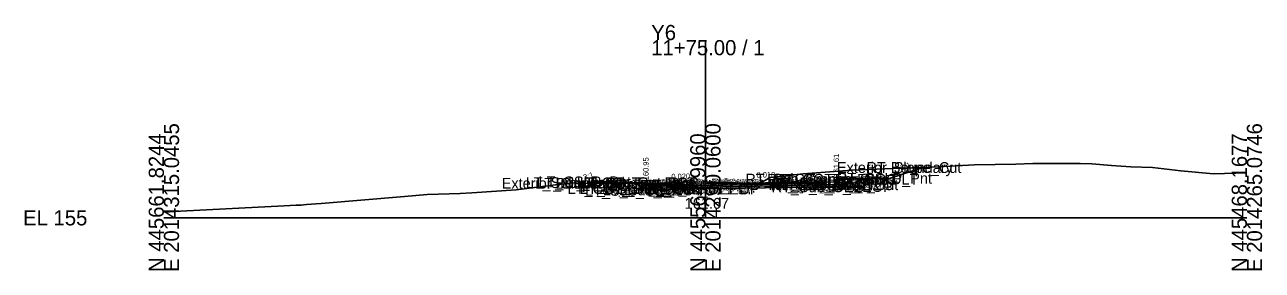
# Model space of a CAD drawing. Extents: x -26 to 203, y -10 to 4529.
# Drawn here: x -25.7 to 202.8, y 3490.3 to 3535.7 of the extents above; entities that cross this region are included whole.
import ezdxf

# ---------------------------------------------------------------- set-up
doc = ezdxf.new("R2010")
doc.units = 0
for name, color, linetype in [('Default', 7, 'Continuous'), ('Exist Cross Section Cell', 7, 'Continuous'), ('Exist XS Center Line Elevation Label', 7, 'Continuous'), ('Exist XS Ground Line', 7, 'Continuous'), ('Prop CMT Conc Surface', 7, 'Continuous'), ('Prop CMT Concrete Structures', 7, 'Continuous'), ('Prop CMT Pvmt Course 1', 7, 'Continuous'), ('Prop CMT Pvmt Course 1 CG', 7, 'Continuous'), ('Prop CMT Pvmt Course 2', 7, 'Continuous'), ('Prop CMT Pvmt Course 3', 7, 'Continuous'), ('Prop CMT Pvmt Surface', 7, 'Continuous'), ('Prop CMT Slope Grass', 7, 'Continuous'), ('Prop CMT Subgrade Earthwork', 7, 'Continuous'), ('Prop XS Earthwork Shape', 7, 'Continuous'), ('Prop XS Hydro Elevations', 7, 'Continuous'), ('Prop XS SE Text', 7, 'Continuous'), ('Prop XS Side Slope Text', 7, 'Continuous'), ('Scratch_Level_0', 7, 'Continuous')]:
    doc.layers.add(name, color=color, linetype=linetype)

msp = doc.modelspace()

# ---------------------------------------------------------------- linework, layer by layer
at = {"layer": 'Exist Cross Section Cell'}
for p, q in [((100, 3500), (100, 3532.84)), ((0, 3500), (100, 3500)), ((100, 3500), (200, 3500))]:
    msp.add_line(p, q, dxfattribs=at)
at = {"layer": 'Exist XS Ground Line'}
msp.add_lwpolyline([(0, 3501.07), (3.09, 3501.2), (22.19, 3502.2), (24.42, 3502.31), (25.33, 3502.36), (25.78, 3502.41), (26.34, 3502.46), (29.04, 3502.66), (44.41, 3503.95), (48.65, 3504.28), (54.74, 3504.48), (56.86, 3504.64), (65.08, 3505.17), (73.28, 3506.19), (75.39, 3506.48), (77.21, 3506.39), (90.34, 3506.37), (95.88, 3506.56), (100.18, 3506.67), (108.03, 3506.36), (109.71, 3506.26), (110.61, 3506.73), (112, 3507.43), (118.09, 3508.13), (127.04, 3508.83), (134.66, 3509.09), (137.48, 3509.17), (138.13, 3509.21), (138.73, 3509.24), (139.6, 3509.26), (149.68, 3509.77), (157.33, 3509.92), (160.45, 3510.05), (167.76, 3510.04), (169.21, 3510.04), (171.39, 3510), (174.97, 3509.68), (178.58, 3509.4), (182.56, 3509.31), (187.8, 3508.71), (193.82, 3508.1), (200, 3508.29)], dxfattribs=at)
at = {"layer": 'Prop CMT Conc Surface'}
for points in [[(89.01, 3505.95), (89, 3506.45), (88.5, 3506.45)], [(91.01, 3506.07), (89.01, 3505.95)], [(122.17, 3506.65), (124.17, 3506.61)], [(124.17, 3506.61), (124.18, 3507.11), (124.68, 3507.11)]]:
    msp.add_lwpolyline(points, dxfattribs=at)
at = {"layer": 'Prop CMT Concrete Structures'}
for points in [[(91.01, 3506.07), (89.01, 3505.95), (89, 3506.45), (88.5, 3506.45)], [(88.5, 3506.45), (88.51, 3505.43), (91.01, 3505.48)], [(91.01, 3505.48), (91.01, 3506.07)], [(122.17, 3506.65), (124.17, 3506.61), (124.18, 3507.11), (124.68, 3507.11)], [(124.68, 3507.11), (124.67, 3506.11), (122.17, 3506.07)], [(122.17, 3506.07), (122.17, 3506.65)]]:
    msp.add_lwpolyline(points, dxfattribs=at)
at = {"layer": 'Prop CMT Pvmt Course 1'}
for points in [[(100, 3506.25), (91.01, 3506.07)], [(91.01, 3506.07), (91.01, 3505.82)], [(91.01, 3505.82), (100, 3506)], [(100, 3506.25), (122.17, 3506.65)], [(122.17, 3506.4), (100, 3506)], [(100, 3506), (100, 3506.25)], [(100, 3506), (100, 3506.25)], [(122.17, 3506.65), (122.17, 3506.4)]]:
    msp.add_lwpolyline(points, dxfattribs=at)
msp.add_lwpolyline([(100, 3506), (100, 3506.12), (100, 3506.12), (100, 3506)], close=True, dxfattribs=at)
msp.add_lwpolyline([(100, 3506), (100, 3506.12), (100, 3506.12), (100, 3506)], close=True, dxfattribs=at)
at = {"layer": 'Prop CMT Pvmt Course 1 CG'}
for points in [[(122.17, 3506.07), (125.17, 3506.12), (125.5, 3505.79)], [(122.17, 3505.73), (122.17, 3506.07)], [(125.5, 3505.79), (122.17, 3505.73)], [(91.01, 3505.48), (88.01, 3505.42), (87.66, 3505.08)], [(87.66, 3505.08), (91.01, 3505.15)], [(91.01, 3505.15), (91.01, 3505.48)]]:
    msp.add_lwpolyline(points, dxfattribs=at)
at = {"layer": 'Prop CMT Pvmt Course 2'}
for points in [[(100, 3506), (91.01, 3505.82)], [(91.01, 3505.82), (91.01, 3505.48)], [(100, 3506), (122.17, 3506.4)], [(122.17, 3506.07), (100, 3505.66)], [(100, 3505.66), (100, 3506)], [(100, 3505.66), (100, 3506)], [(122.17, 3506.4), (122.17, 3506.07)], [(91.01, 3505.48), (100, 3505.66)]]:
    msp.add_lwpolyline(points, dxfattribs=at)
at = {"layer": 'Prop CMT Pvmt Course 3'}
for points in [[(100, 3505.66), (122.17, 3506.07)], [(122.17, 3505.73), (100, 3505.33)], [(122.17, 3506.07), (122.17, 3505.73)], [(100, 3505.66), (91.01, 3505.48)], [(91.01, 3505.48), (91.01, 3505.15)], [(91.01, 3505.15), (100, 3505.33)], [(100, 3505.33), (100, 3505.66)], [(100, 3505.33), (100, 3505.66)]]:
    msp.add_lwpolyline(points, dxfattribs=at)
at = {"layer": 'Prop CMT Pvmt Surface'}
for points in [[(100, 3506.25), (91.01, 3506.07)], [(100, 3506.25), (122.17, 3506.65)]]:
    msp.add_lwpolyline(points, dxfattribs=at)
at = {"layer": 'Prop CMT Slope Grass'}
for points in [[(124.68, 3507.11), (134.18, 3507.3), (140.15, 3509.29)], [(88.5, 3506.45), (79, 3506.64), (78.25, 3506.38)]]:
    msp.add_lwpolyline(points, dxfattribs=at)
at = {"layer": 'Prop CMT Subgrade Earthwork'}
for points in [[(91.01, 3505.15), (87.66, 3505.08), (86.26, 3506.49)], [(100, 3505.33), (122.17, 3505.73)], [(122.17, 3505.73), (125.5, 3505.79), (126.86, 3507.15)], [(100, 3505.33), (91.01, 3505.15)]]:
    msp.add_lwpolyline(points, dxfattribs=at)
at = {"layer": 'Prop XS Earthwork Shape'}
for points in [[(127.04, 3508.83), (134.66, 3509.09), (137.48, 3509.17), (138.13, 3509.21), (138.73, 3509.24), (139.6, 3509.26), (140.15, 3509.29), (134.18, 3507.3), (126.86, 3507.15), (124.68, 3507.11), (124.18, 3507.11), (124.17, 3506.61), (122.17, 3506.65), (110.03, 3506.43), (110.61, 3506.73), (112, 3507.43), (118.09, 3508.13)], [(86.37, 3506.37), (86.26, 3506.49), (79, 3506.64), (78.25, 3506.38)], [(87.66, 3505.08), (86.37, 3506.37), (88.5, 3506.37), (88.51, 3505.43), (91.01, 3505.48), (91.01, 3506.07), (100, 3506.25), (107.46, 3506.38), (108.03, 3506.36), (109.71, 3506.26), (110.03, 3506.43), (122.17, 3506.65), (122.17, 3506.07), (124.67, 3506.11), (124.68, 3507.11), (126.86, 3507.15), (125.5, 3505.79), (122.17, 3505.73), (100, 3505.33), (91.01, 3505.15)], [(88.5, 3506.37), (89, 3506.37), (89.01, 3505.95), (91.01, 3506.07), (91.01, 3505.48), (88.51, 3505.43)], [(100, 3506.25), (107.46, 3506.38), (100.18, 3506.67), (95.88, 3506.56), (90.34, 3506.37), (89, 3506.37), (89.01, 3505.95), (91.01, 3506.07)], [(124.17, 3506.61), (124.18, 3507.11), (124.68, 3507.11), (124.67, 3506.11), (122.17, 3506.07), (122.17, 3506.65)]]:
    msp.add_lwpolyline(points, close=True, dxfattribs=at)

# ---------------------------------------------------------------- texts
at = {"layer": 'Default'}
msp.add_text('-', height=0.0001, dxfattribs=at).set_placement((0, 3500))
at = {"layer": 'Exist Cross Section Cell'}
for s, p in [('Y6', (90, 3532.84)), ('11+75.00 / 1', (90, 3530.04)), ('EL 155', (-26, 3498.6))]:
    msp.add_text(s, height=2.8, dxfattribs=at).set_placement(p)
for s, p in [('E 2014315.0455', (2.8, 3490)), ('E 2014290.0600', (102.8, 3490)), ('E 2014265.0746', (202.8, 3490)), ('N 445661.8244', (0, 3490)), ('N 445564.9960', (100, 3490)), ('N 445468.1677', (200, 3490))]:
    msp.add_text(s, height=2.8, rotation=90, dxfattribs=at).set_placement(p)
at = {"layer": 'Exist XS Center Line Elevation Label'}
msp.add_text('161.67', height=2, dxfattribs=at).set_placement((96.18, 3501.67))
at = {"layer": 'Prop XS Hydro Elevations'}
for s, p in [('160.95', (89.51, 3506.95)), ('161.61', (124.67, 3507.61))]:
    msp.add_text(s, height=1, rotation=90, dxfattribs=at).set_placement(p)
at = {"layer": 'Prop XS SE Text'}
for s, rotation, p in [('0.020', 1.1458, (93.73, 3507.12)), ('0.018', 1.0447, (109.45, 3507.42))]:
    msp.add_text(s, height=1, rotation=rotation, dxfattribs=at).set_placement(p)
at = {"layer": 'Prop XS Side Slope Text'}
for p in [(77.64, 3506.97), (136.18, 3508.75)]:
    msp.add_text('3:1', height=1, rotation=18.4332, dxfattribs=at).set_placement(p)
at = {"layer": 'Scratch_Level_0'}
for s, p in [('Exterior Boundary', (124.29, 3508.29)), ('RT_Slope_Cut', (129.74, 3508.29)), ('RT_Sub_Trench_Out_DLT', (107.38, 3506.15)), ('RT_CG_Top_Face', (111.39, 3506.11)), ('RT_CG_Top_BOC', (112.91, 3506.11)), ('RT_CSLP_Pnt', (124.3, 3506.3)), ('Exterior Boundary', (62.39, 3505.38)), ('LT_Sub_Trench_Out_DLT', (66.82, 3505.49)), ('LT_Slope_Fill', (68.77, 3505.38)), ('LT_CSLP_Pnt', (69.18, 3505.64)), ('LT_CG1_Shelf_Out', (74.56, 3504.42)), ('LT_CG_Top_Face', (76.26, 3505.45)), ('LT_CG_Top_BOC', (76.79, 3505.45)), ('LT_CG_Bot_BOC', (76.82, 3504.43)), ('LT_CG_Top_Gut', (77.24, 3504.95)), ('LT_Sub_OEOP', (77.78, 3504.08)), ('LT_CG_Bot_IE', (80.92, 3504.48)), ('LT_Sub_OEOT', (81.08, 3504.15)), ('LT_PV2_OEOT', (81.18, 3504.82)), ('LT_PV3_OEOT', (81.18, 3504.48)), ('LT_PV1_OEOT', (81.75, 3505.07)), ('RT_Sub_OEEOP', (89.17, 3504.33)), ('LT_Sub_OEEOP', (89.21, 3504.33)), ('RT_PV2_OEEOP', (89.26, 3505)), ('RT_PV3_OEEOP', (89.26, 3504.66)), ('LT_PV2_OEEOP', (89.31, 3505)), ('LT_PV3_OEEOP', (89.31, 3504.66)), ('RT_PV1_OEEOP', (89.83, 3505.12)), ('LT_PV1_OEEOP', (89.87, 3505.12)), ('RT_PV2_IEEOP', (89.91, 3505)), ('LT_PV2_IEEOP', (89.95, 3505)), ('RT_PV1_IEEOP', (90.47, 3505.12)), ('LT_PV1_IEEOP', (90.52, 3505.12)), ('PV2_PGL', (93.91, 3505)), ('PV1_PGL', (94.47, 3505.25)), ('RT_CG1_Shelf_Out', (111.68, 3505.12)), ('RT_CG_Bot_IE', (112.04, 3505.07)), ('RT_Sub_OEOT', (112.21, 3504.73)), ('RT_PV2_OEOT', (112.3, 3505.4)), ('RT_PV3_OEOT', (112.3, 3505.07)), ('RT_CG_Top_Gut', (112.36, 3505.61)), ('RT_PV1_OEOT', (112.87, 3505.65)), ('RT_CG_Bot_BOC', (112.94, 3505.11)), ('RT_Sub_OEOP', (115.56, 3504.79))]:
    msp.add_text(s, height=2, dxfattribs=at).set_placement(p)

doc.saveas('drawing.dxf')
